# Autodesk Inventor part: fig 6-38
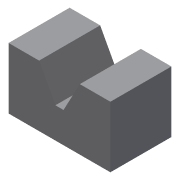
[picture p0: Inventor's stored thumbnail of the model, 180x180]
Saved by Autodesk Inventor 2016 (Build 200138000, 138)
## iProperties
Created: 2005-12
Part Number: fig 6-38
Document SubType Name: Modeling
Designer: CADCIM
Density: 1 g/cm^3
Material: Generic
Appearance: Default
Author: CADCIM
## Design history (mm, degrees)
sketch "Sketch1"
  geometry: L1 (10, 15)-(25, 15); L2 (25, 15)-(25, -15); L3 (25, -15)-(-25, -15); L4 (-25, -15)-(-25, 15); L5 (-25, 15)-(-10, 15); L6 (-10, 15)-(-2, 0); L7 (-2, 0)-(2, 0); L8 (2, 0)-(10, 15); 1 further point
  constraints: 16 end point, 3 equal length, 3 parallel, 1 collinear, 1 horizontal, 1 perpendicular, 1 other
  dimensions: "d0" = 50 distance of L2.end L3.end; "d1" = 25 distance from line of point (0, 0) L2; "d2" = 30 distance of L1.end L2.end; "d3" = 15 distance of L1.start L1.end; "d4" = 15 distance between parallel lines of L1 L7; "d5" = 4 distance of L6.end L7.end; "d6" = 15 distance from line of point (0, 0) L3
extrude "Extrusion1" new body sketch "Sketch1" stored distance "d7" = 30; taper "d8" = 0 deg
body "Solid1"
